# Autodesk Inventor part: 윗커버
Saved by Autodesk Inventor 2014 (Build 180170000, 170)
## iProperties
Created: 2026-03
Part Number: 윗커버
Material: 강철, 주조
Document SubType Name: Modeling
Designer: dg
Density: 7.85 g/cm^3
Appearance: 강철 - 주조
Mass: 193.231 g
Surface Area: 84.6209 cm^2
Volume: 24.6154 cm^3
Author: jhkim
Creation Date: 2025-06-27
Sending System: Autodesk Inventor 2026
Preprocessor: ST-DEVELOPER v20.1
Author: dg
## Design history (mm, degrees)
node "윗커버1"
node "솔리드1"
node "기준1"
